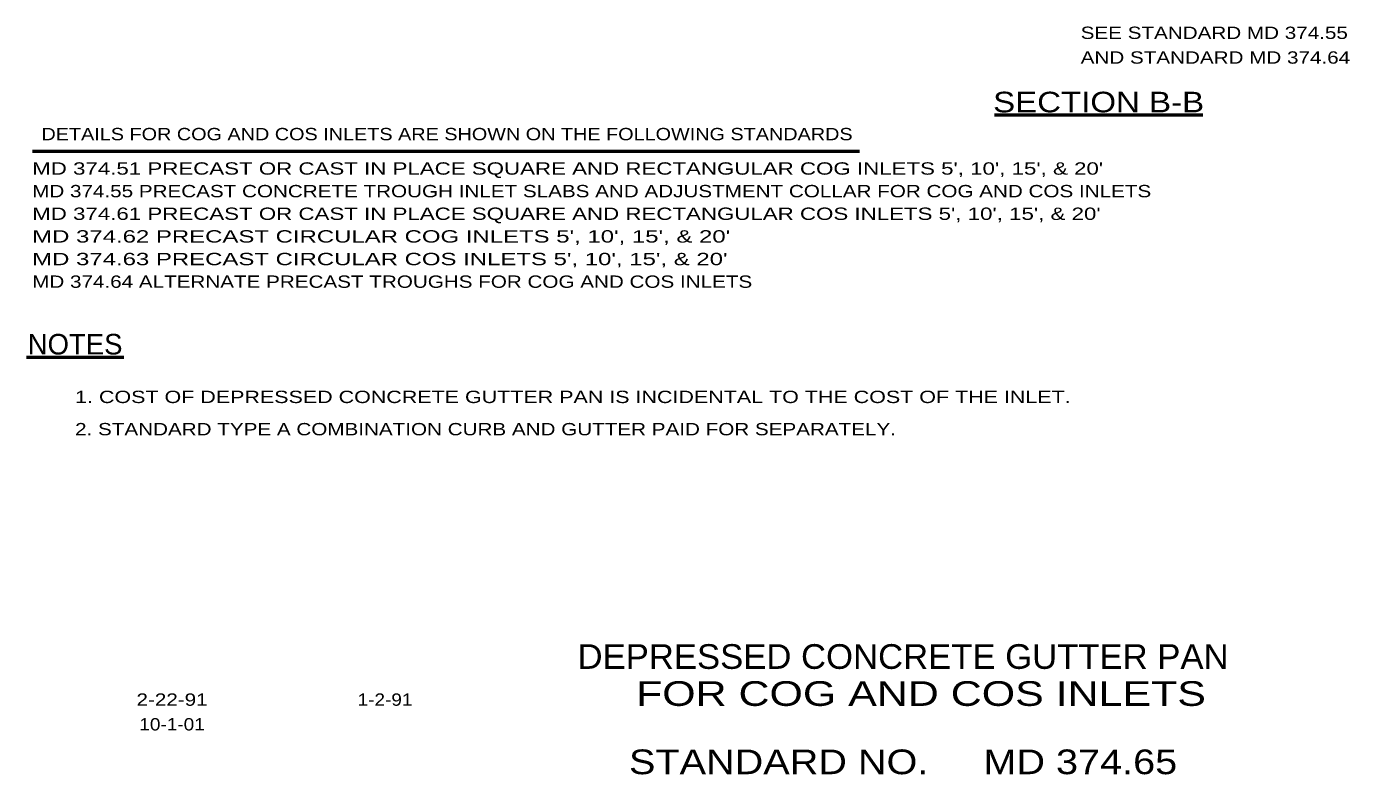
# Model space of a CAD drawing. Extents: x 16.6 to 31.7, y 5.4 to 26.
# Drawn here: x 18.06 to 31.73, y 5.38 to 13.11 of the extents above; entities that cross this region are included whole.
import ezdxf
from ezdxf.enums import TextEntityAlignment as Align

# ---------------------------------------------------------------- set-up
doc = ezdxf.new("R2010")
doc.units = 0
doc.header["$LTSCALE"] = 0.051
doc.layers.add('12', color=7, linetype='Continuous', lineweight=53)
doc.layers.add('13', color=7, linetype='Continuous', lineweight=53)

msp = doc.modelspace()

# ---------------------------------------------------------------- linework, layer by layer
at = {"layer": '12'}
msp.add_line((28.06258, 12.194), (30.21275, 12.194), dxfattribs=at)
at = {"layer": '13'}
for p, q in [((18.125, 11.82042), (26.66825, 11.82042)), ((18.064, 9.69275), (19.06883, 9.69275))]:
    msp.add_line(p, q, dxfattribs=at)

# ---------------------------------------------------------------- texts
at = {"layer": '12', "width": 1.25}
for s, p in [('SEE STANDARD MD 374.55', (28.95258, 12.97825)), ('AND STANDARD MD 374.64', (28.95258, 12.72325))]:
    msp.add_text(s, height=0.1275, dxfattribs=at).set_placement(p)
at = {"layer": '12', "width": 1.2}
msp.add_text('SECTION B-B', height=0.2125, dxfattribs=at).set_placement((29.13771, 12.22075), align=Align.CENTER)
at = {"layer": '13'}
for s, height, width, p in [('DETAILS FOR COG AND COS INLETS ARE SHOWN ON THE FOLLOWING STANDARDS', 0.1275, 1.2, (22.408, 11.93217)), ('DEPRESSED CONCRETE GUTTER PAN', 0.255, 1.05, (27.11825, 6.47242)), ('   FOR COG AND COS INLETS', 0.255, 1.3, (27.11825, 6.08992)), ('2-22-91', 0.1275, 1.25, (19.56783, 6.09108)), ('1-2-91', 0.1275, 1.15, (21.76758, 6.09108)), ('10-1-01', 0.1275, 1.15, (19.56783, 5.83608)), ('STANDARD NO.     MD 374.65', 0.255, 1.2, (27.11829, 5.3845))]:
    msp.add_text(s, height=height, dxfattribs=dict(at, width=width)).set_placement(p, align=Align.CENTER)
for s, width, p in [("MD 374.51 PRECAST OR CAST IN PLACE SQUARE AND RECTANGULAR COG INLETS 5', 10', 15', & 20'", 1.35, (18.12308, 11.57683)), ('MD 374.55 PRECAST CONCRETE TROUGH INLET SLABS AND ADJUSTMENT COLLAR FOR COG AND COS INLETS', 1.25, (18.12308, 11.34308)), ("MD 374.61 PRECAST OR CAST IN PLACE SQUARE AND RECTANGULAR COS INLETS 5', 10', 15', & 20'", 1.35, (18.12308, 11.10933)), ("MD 374.62 PRECAST CIRCULAR COG INLETS 5', 10', 15', & 20'", 1.45, (18.12308, 10.87558)), ("MD 374.63 PRECAST CIRCULAR COS INLETS 5', 10', 15', & 20'", 1.45, (18.12308, 10.64183)), ('MD 374.64 ALTERNATE PRECAST TROUGHS FOR COG AND COS INLETS', 1.25, (18.12308, 10.40808)), ('1. COST OF DEPRESSED CONCRETE GUTTER PAN IS INCIDENTAL TO THE COST OF THE INLET.', 1.3, (18.56633, 9.21783)), ('2. STANDARD TYPE A COMBINATION CURB AND GUTTER PAID FOR SEPARATELY.', 1.25, (18.56633, 8.8845))]:
    msp.add_text(s, height=0.1275, dxfattribs=dict(at, width=width)).set_placement(p)
msp.add_text('NOTES', height=0.2125, dxfattribs=at).set_placement((18.56633, 9.7195), align=Align.CENTER)

doc.saveas('drawing.dxf')
